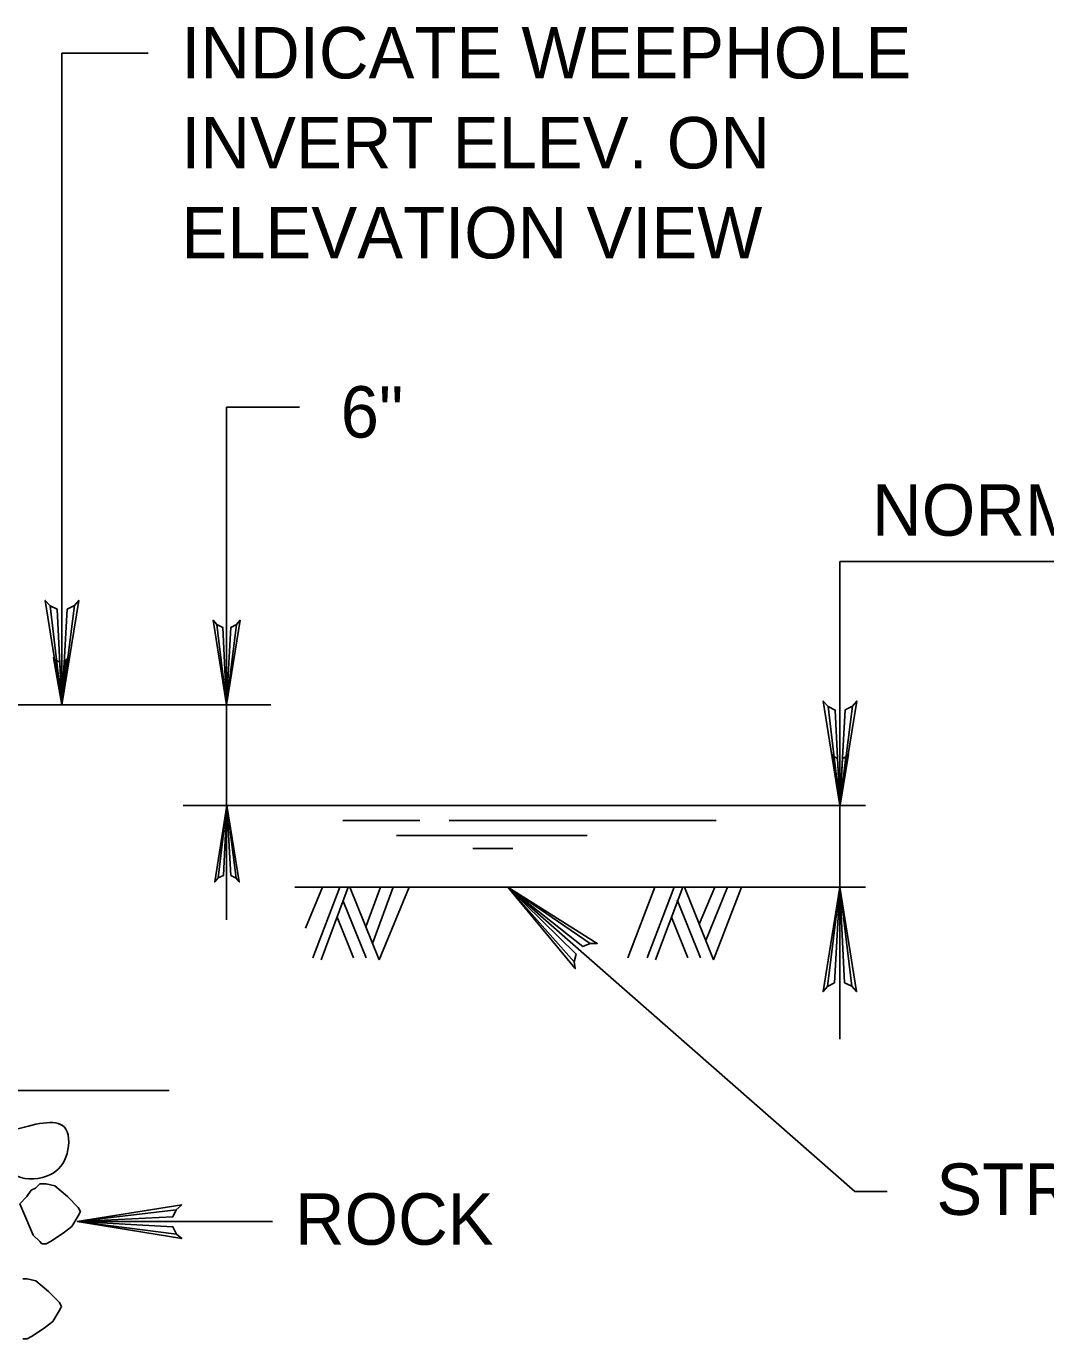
# Model space of a CAD drawing. Extents: x 639028 to 639883, y 298843 to 300031.
# Drawn here: x 639524.2 to 639583.6, y 299566.7 to 299643.3 of the extents above; entities that cross this region are included whole.
import ezdxf

# ---------------------------------------------------------------- set-up
doc = ezdxf.new("R2010")
doc.units = 0
doc.layers.add('2', color=7, linetype='Continuous')
doc.layers.add('52', color=7, linetype='Continuous')

msp = doc.modelspace()

# ---------------------------------------------------------------- linework, layer by layer
at = {"layer": '2'}
for p, q in [((639526.239, 299641.731), (639531.272, 299641.731)), ((639526.239, 299603.704), (639526.239, 299641.731)), ((639535.839, 299591.162), (639535.839, 299621.079)), ((639535.839, 299621.079), (639540.089, 299621.079)), ((639571.614, 299597.829), (639571.614, 299612.079)), ((639571.614, 299612.079), (639609.989, 299612.079)), ((639505.364, 299603.704), (639538.418, 299603.704)), ((639533.318, 299597.829), (639573.114, 299597.829)), ((639536.089, 299597.829), (639537.339, 299597.829)), ((639571.614, 299597.829), (639571.614, 299584.204)), ((639542.614, 299596.954), (639547.118, 299596.954)), ((639548.828, 299596.954), (639564.392, 299596.954)), ((639545.75, 299596.079), (639556.867, 299596.079)), ((639550.196, 299595.329), (639552.534, 299595.329)), ((639539.818, 299593.079), (639573.114, 299593.079)), ((639541.438, 299593.079), (639540.453, 299590.689)), ((639542.441, 299593.079), (639540.864, 299588.954)), ((639542.943, 299593.079), (639541.364, 299588.829)), ((639543.039, 299593.079), (639544.739, 299588.829)), ((639543.965, 299590.764), (639544.818, 299593.079)), ((639544.352, 299589.797), (639545.568, 299593.079)), ((639546.489, 299593.079), (639544.739, 299588.829)), ((639552.239, 299593.079), (639572.489, 299575.329)), ((639560.818, 299593.079), (639559.241, 299588.954)), ((639561.943, 299593.079), (639560.366, 299588.954)), ((639562.444, 299593.079), (639560.866, 299588.829)), ((639562.541, 299593.079), (639564.241, 299588.829)), ((639563.404, 299590.921), (639564.313, 299593.079)), ((639563.791, 299589.953), (639565.065, 299593.079)), ((639565.866, 299593.079), (639564.241, 299588.829)), ((639542.64, 299592.265), (639543.989, 299588.954)), ((639562.116, 299592.329), (639563.491, 299588.954)), ((639542.291, 299591.325), (639543.239, 299588.954)), ((639561.793, 299591.325), (639562.741, 299588.954)), ((639515.864, 299581.204), (639532.489, 299581.204)), ((639572.489, 299575.329), (639574.364, 299575.329)), ((639527.129, 299573.567), (639538.516, 299573.567))]:
    msp.add_line(p, q, dxfattribs=at)
for points in [[(639526.489, 299606.329), (639526.364, 299606.204), (639526.239, 299603.704), (639526.489, 299606.329), (639526.614, 299606.454), (639526.239, 299603.704), (639526.114, 299606.204), (639525.864, 299606.329), (639526.239, 299603.704), (639525.739, 299606.454), (639525.864, 299606.329)], [(639571.267, 299600.689), (639571.477, 299600.572), (639571.625, 299597.859), (639571.267, 299600.689), (639571.142, 299600.829), (639571.625, 299597.859), (639571.758, 299600.572), (639571.96, 299600.677), (639571.625, 299597.859), (639572.108, 299600.829), (639571.96, 299600.677)], [(639524.693, 299575.52), (639524.943, 299575.77)], [(639524.943, 299575.77), (639525.068, 299575.77)], [(639525.068, 299575.77), (639525.318, 299575.77)], [(639525.318, 299575.77), (639525.818, 299575.645)], [(639525.818, 299575.645), (639526.568, 299575.02)], [(639523.781, 299574.608), (639524.193, 299575.02)], [(639524.193, 299575.02), (639524.443, 299575.395)], [(639524.443, 299575.395), (639524.693, 299575.52)], [(639526.568, 299575.02), (639527.193, 299574.395)], [(639524.193, 299573.645), (639523.781, 299574.608)], [(639527.193, 299574.395), (639527.318, 299574.145)], [(639527.318, 299574.145), (639527.193, 299573.895)], [(639524.568, 299572.77), (639524.193, 299573.645)], [(639526.818, 299573.27), (639526.318, 299572.895)], [(639527.193, 299573.895), (639526.818, 299573.27)], [(639524.943, 299572.395), (639524.568, 299572.77)], [(639526.318, 299572.895), (639525.568, 299572.395)], [(639525.068, 299572.27), (639524.943, 299572.395)], [(639525.318, 299572.27), (639525.068, 299572.27)], [(639525.568, 299572.395), (639525.318, 299572.27)], [(639523.96, 299570.229), (639524.21, 299570.229)], [(639524.21, 299570.229), (639524.71, 299570.104)], [(639524.71, 299570.104), (639525.46, 299569.479)], [(639525.46, 299569.479), (639526.085, 299568.854)], [(639526.085, 299568.854), (639526.21, 299568.604)], [(639526.085, 299568.354), (639525.71, 299567.729)], [(639526.21, 299568.604), (639526.085, 299568.354)], [(639525.21, 299567.354), (639524.46, 299566.854)], [(639525.71, 299567.729), (639525.21, 299567.354)], [(639524.21, 299566.729), (639523.96, 299566.729)], [(639524.46, 299566.854), (639524.21, 299566.729)]]:
    msp.add_lwpolyline(points, dxfattribs=at)
msp.add_spline([(639523.597, 299578.956), (639526.472, 299578.956), (639526.472, 299577.331), (639525.347, 299576.206), (639523.472, 299576.331), (639523.597, 299578.956)], degree=3, dxfattribs=at)
at = {"layer": '52'}
for points in [[(639526.967, 299609.504), (639526.547, 299609.288), (639526.239, 299603.704), (639526.967, 299609.504), (639527.222, 299609.801), (639526.239, 299603.704), (639525.963, 299609.283), (639525.548, 299609.487), (639526.239, 299603.704), (639525.27, 299609.801), (639525.548, 299609.487)], [(639536.428, 299608.402), (639536.088, 299608.227), (639535.839, 299603.704), (639536.428, 299608.402), (639536.634, 299608.643), (639535.839, 299603.704), (639535.615, 299608.223), (639535.279, 299608.389), (639535.839, 299603.704), (639535.054, 299608.643), (639535.279, 299608.389)], [(639572.342, 299603.629), (639571.922, 299603.413), (639571.614, 299597.829), (639572.342, 299603.629), (639572.597, 299603.926), (639571.614, 299597.829), (639571.338, 299603.408), (639570.923, 299603.612), (639571.614, 299597.829), (639570.645, 299603.926), (639570.923, 299603.612)], [(639536.394, 299593.601), (639536.088, 299593.759), (639535.864, 299597.829), (639536.394, 299593.601), (639536.58, 299593.385), (639535.864, 299597.829), (639535.662, 299593.762), (639535.36, 299593.614), (639535.864, 299597.829), (639535.157, 299593.385), (639535.36, 299593.614)], [(639556.12, 299588.709), (639556.235, 299589.167), (639552.239, 299593.079), (639556.12, 299588.709), (639556.176, 299588.322), (639552.239, 299593.079), (639556.616, 299589.609), (639557.044, 299589.787), (639552.239, 299593.079), (639557.463, 299589.789), (639557.044, 299589.787)], [(639570.886, 299587.28), (639571.306, 299587.496), (639571.614, 299593.079), (639570.886, 299587.28), (639570.632, 299586.982), (639571.614, 299593.079), (639571.89, 299587.5), (639572.305, 299587.296), (639571.614, 299593.079), (639572.583, 299586.982), (639572.305, 299587.296)], [(639532.929, 299572.839), (639532.713, 299573.259), (639527.129, 299573.567), (639532.929, 299572.839), (639533.226, 299572.585), (639527.129, 299573.567), (639532.708, 299573.843), (639532.912, 299574.258), (639527.129, 299573.567), (639533.226, 299574.536), (639532.912, 299574.258)]]:
    msp.add_lwpolyline(points, dxfattribs=at)

# ---------------------------------------------------------------- texts
at = {"layer": '2'}
for s, p in [('INDICATE WEEPHOLE', (639533.203, 299640.255)), ('INVERT ELEV. ON', (639533.203, 299635.005)), ('ELEVATION VIEW', (639533.203, 299629.755)), ('6"', (639542.497, 299619.301)), ('NORMAL WATER', (639573.489, 299613.579)), ('STREAM BED', (639577.239, 299573.954)), ('ROCK', (639539.827, 299572.212))]:
    msp.add_text(s, height=3, dxfattribs=at).set_placement(p)

doc.saveas('drawing.dxf')
